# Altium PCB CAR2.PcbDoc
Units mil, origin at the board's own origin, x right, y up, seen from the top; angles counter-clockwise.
Board outline 1397.98 x 964.91 mil, 2 copper layers (Top Layer, Bottom Layer); 47 components, 32 nets, 165 pads, 34 vias.
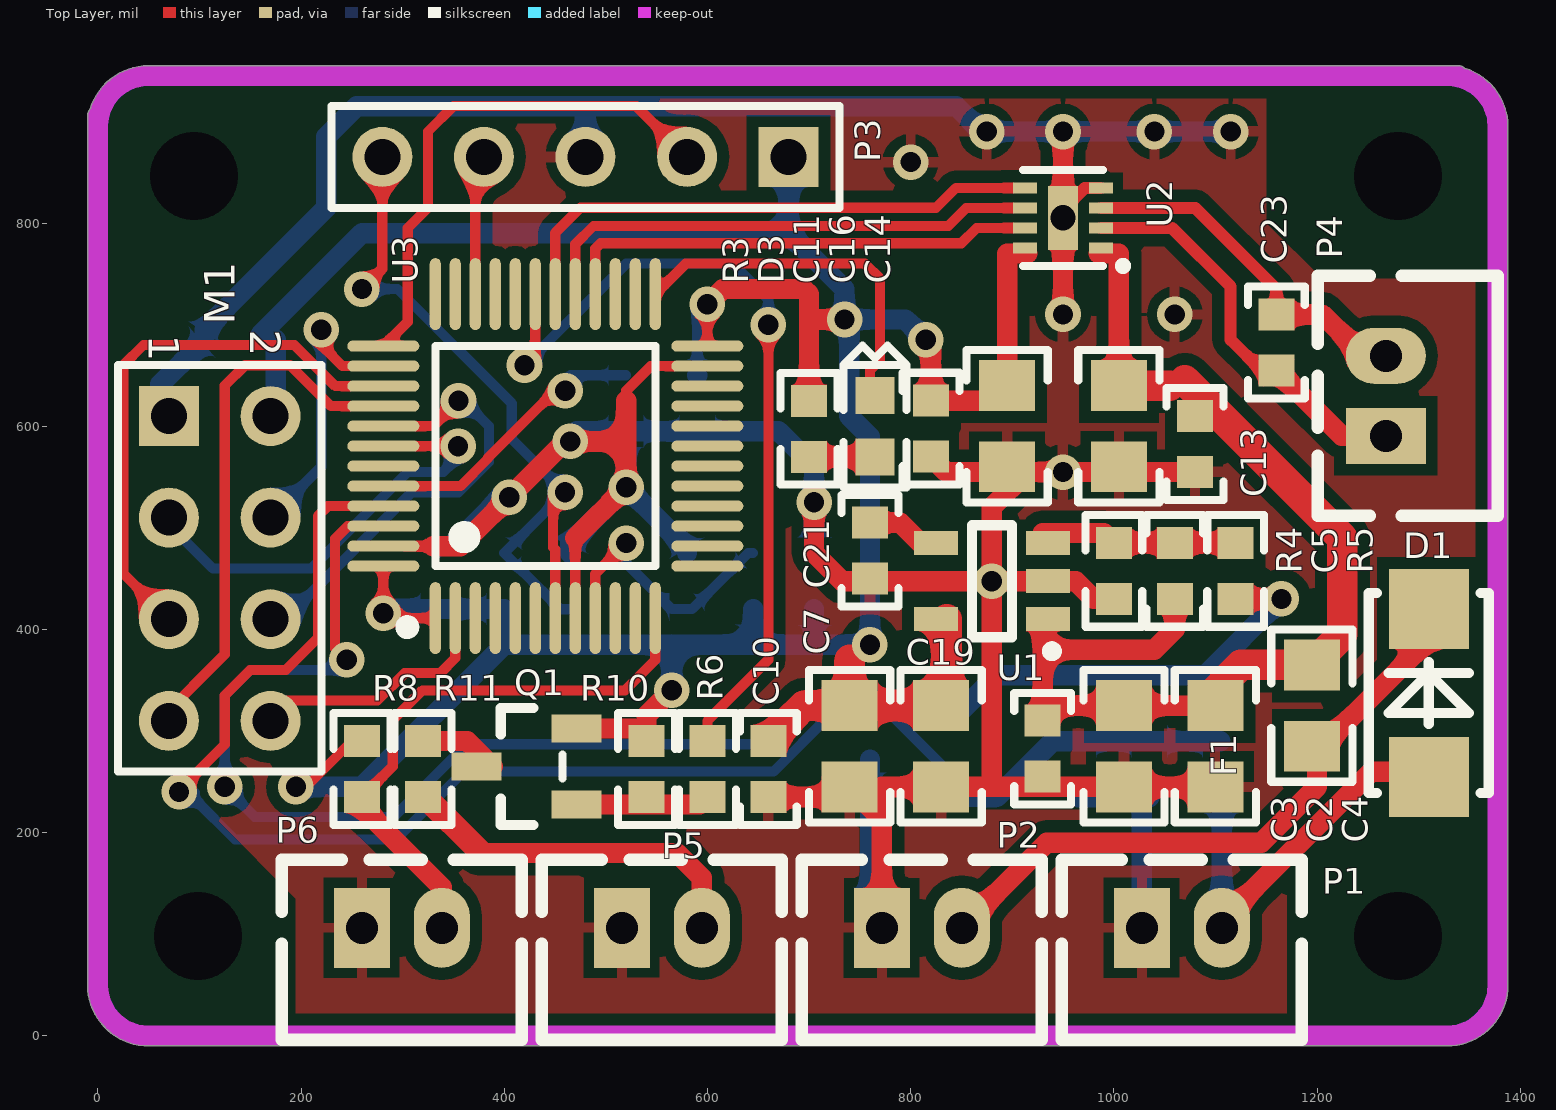
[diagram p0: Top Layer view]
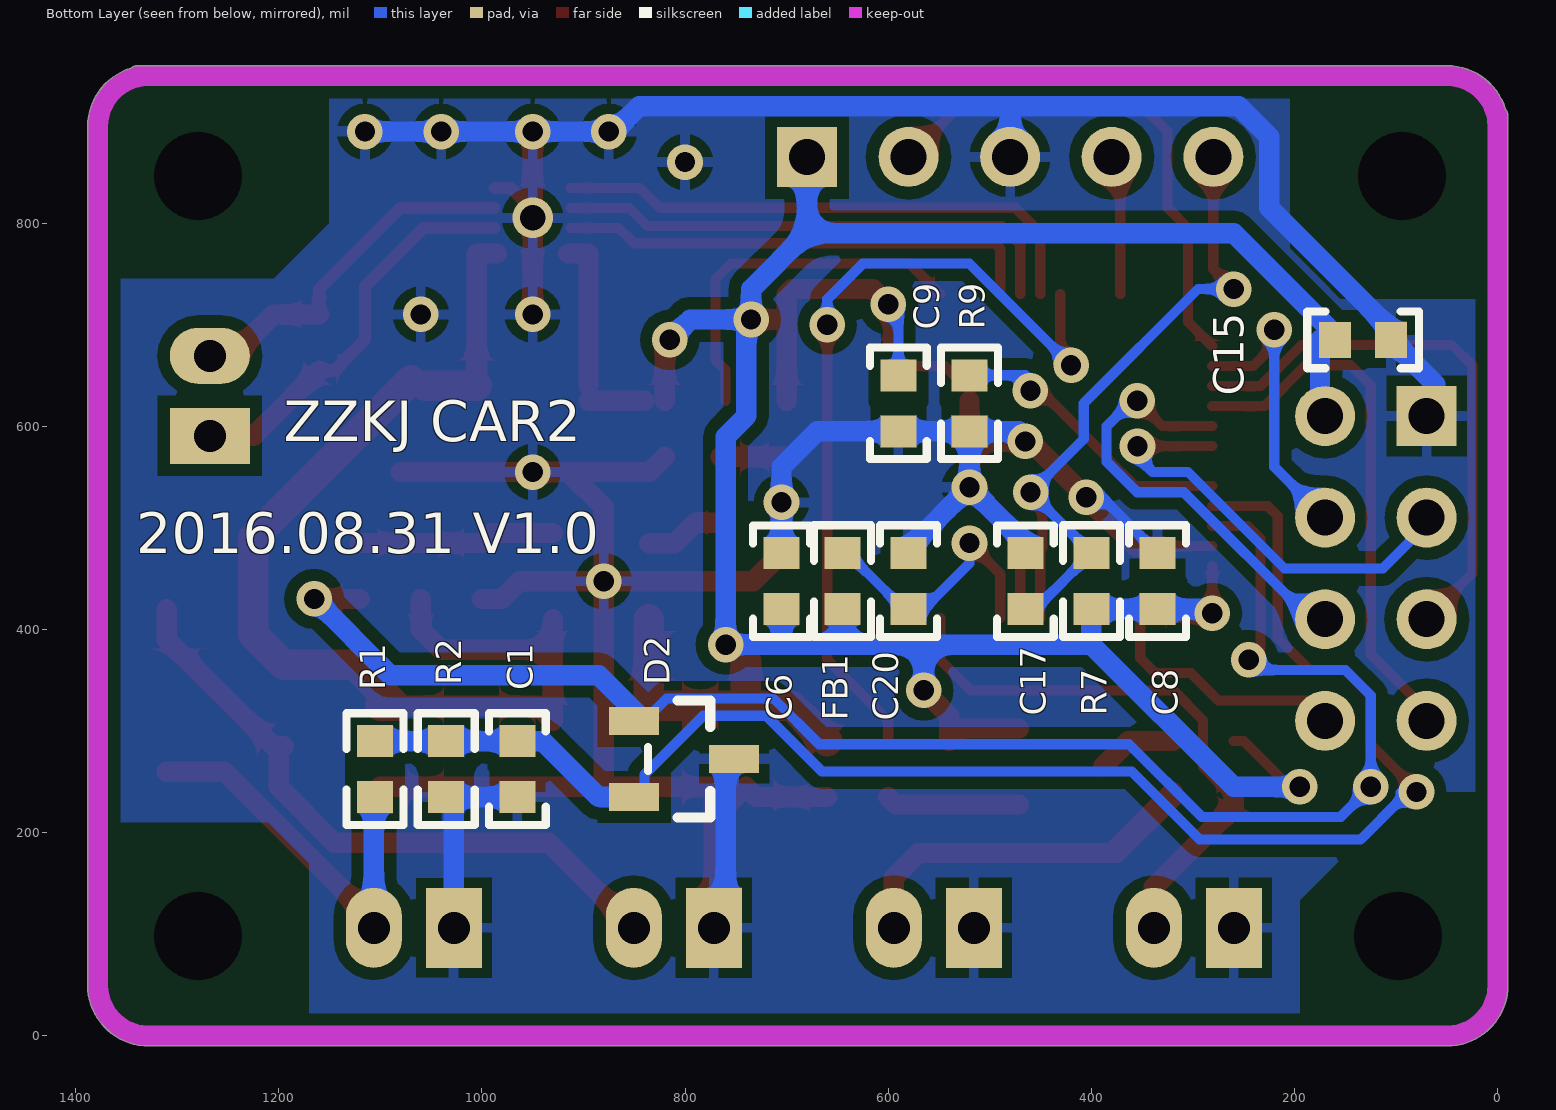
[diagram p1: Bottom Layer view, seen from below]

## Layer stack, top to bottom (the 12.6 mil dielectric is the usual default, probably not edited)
Top Solder: solder mask 0.4, Solder Resist, Dk 3.5
Top Layer: signal copper 1.4
Dielectric 1: dielectric 12.6, FR-4, Dk 4.8
Bottom Layer: signal copper 1.4
Bottom Solder: solder mask 0.4, Solder Resist, Dk 3.5

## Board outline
-10.01,50 -10.01,905.51 cw(c0,905.51) -7.47,912.19 cw(c50,894.88) 50,954.9 1338.58,954.9 cw(c1338.58,944.88) 1345.26,952.35 cw(c1327.95,894.88) 1387.97,894.88 1387.97,50 cw(c1327.95,50) 1327.95,-10.01 50,-10.01 cw(c50,50)

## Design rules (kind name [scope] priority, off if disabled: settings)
Clearance Clearance_1 [InPolygon] p1: gap=12
Clearance [All] p2: gap=7
PolygonConnect [All] p1: connectstyle=Relief reliefconductorwidth=10 reliefentries=4 polygonreliefangle="90 Angle" airgapwidth=10
RoutingVias [All] p1: holewidth=22 width=40 viastyle="Through Hole" minholewidth=20 minwidth=30 maxholewidth=30 maxwidth=50
SilkToSolderMaskClearance [IsPad] p1: minsilkscreentomaskgap=4 clearancetoexposedcopper=TRUE
SolderMaskExpansion [All] p1: expansion=4
Width [All] p1: maxlimit=50 minlimit=10 preferedwidth=20 minimp=50.000000 maximp=50.000000 favimp=50.000000
29 further rules are at their usual default settings.

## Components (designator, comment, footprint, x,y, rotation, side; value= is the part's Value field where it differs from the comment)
C1 "100nF" C0603 965,234.88 r90 bottom
C2 "10uF" C0805 1010,285 r270 top
C3 "100nF" C0603 930,255 r90 top
C4 "10uF" C0805 1100,285 r270 top
C5 "100nF" C0603 1060,485.12 r270 top
C6 "100nF" C0603 705,419.88 r90 bottom
C7 "10uF" C0805 740,285 r270 top
C8 "100nF" C0603 335,475.12 r270 bottom
C9 "100nF" C0603 590,595 r90 bottom
C10 "100nF" C0603 660,290.12 r270 top
C11 "100nF" C0603 820,570 r90 top
C13 "100nF" C0603 1080,554.88 r90 top
C14 "10uF" C0805 1005,600 r90 top
C15 "100nF" C0603 105,685 r0 bottom
C16 "10uF" C0805 895,600 r90 top
C17 "100nF" C0603 465,475 r270 bottom
C19 "10uF" C0805 830,285 r90 top
C20 "100nF" C0603 580,475.12 r270 bottom
C21 "100nF" C0603 760,505 r270 top
C23 "100nF" C0603 1160,710 r270 top
D1 "SS14" LC-SMA(DO-214AC)_S2 1310,337.32 r270 top
D2 "PESD3V3L2BT" LC-SOT-23(SOT-23-3) 800.79,272.4 r0 bottom
D3 "LEDV1" LC-0603_LED_S4 765,600 r270 top
F1 "SMD0805-110" R0805 1195,325 r90 top
FB1 "GZ1608D601TF" R0603 645,420 r90 bottom
M1 "NRF2401" HDR2X4 70,610 r270 top
P1 "5V IN" PH-2Y 1027.56,106.3 r0 top
P2 "BAT" PH-2Y 771.65,106.3 r0 top
P3 "SWD" HDR1X5 680,865 r180 top
P4 "Motor" PH-2Y 1267.72,590.55 r90 top
P5 "TX" PH-2Y 515.75,106.3 r0 top
P6 "RX" PH-2Y 259.84,106.3 r0 top
Q1 "Si2301CDS" LC-SOT-23(SOT-23-3) 422.13,265 r0 top
R1 "10K" R0603 1105,290 r270 bottom
R2 "10K" R0603 1035,234.88 r90 bottom
R3 "1.5K" R0603 700,569.88 r90 top
R4 "100K" R0603 1000,430 r90 top
R5 "10K" R0603 1120,430 r90 top
R6 "1K" R0603 600,235 r90 top
R7 "100K" R0603 400,475.12 r270 bottom
R8 "100K" R0603 260,290.12 r270 top
R9 "10K" R0603 520,595 r90 bottom
R10 "100K" R0603 540,290.12 r270 top
R11 "100" R0603 320,290.12 r270 top
U1 "MIC5205-3.3YM5" LC-SOT-23-5 880,447.4 r0 top
U2 "DRV8837DSGR" "LC-WSON-8_2x2mm - DRV8837" 950,805 r90 top
U3 "STM32F051C8T6" LC-LQFP-48_7x7x05P 440.47,570.55 r0 top

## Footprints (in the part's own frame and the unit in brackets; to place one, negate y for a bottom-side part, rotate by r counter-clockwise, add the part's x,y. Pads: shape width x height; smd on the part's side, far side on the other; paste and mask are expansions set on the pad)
C0603 [mm] "Chip Capacitor, Body 1.6x0.8mm, IPC High Density"
  rect 0.8x0.9 smd: 1(0,0) 2(1.4,0)
  silkscreen extent -0.7,-0.71 2.1,0.71, body extent -0.18,-0.48 1.57,0.47, height 1.3
C0805 [mil] "Chip Capacitor, Body 2.0x1.3mm, IPC High Density"
  rect 50x55.12 smd: 1(-40,0) 2(40,0)
  silkscreen extent -75,-40 75,40, body extent -43,-30 43,30, height 55
HDR1X5 [mm] "Connector; Header; 5 Position"
  rect 1.5x1.5 hole 0.9: 1(0,0)
  round 1.5 hole 0.9: 2(2.54,0) 3(5.08,0) 4(7.62,0) 5(10.16,0)
  silkscreen extent -1.27,-1.27 11.43,1.27
HDR2X4 [mm] "Connector; Header; 4x2 Position"
  rect 1.5x1.5 hole 0.9: 1(0,0)
  round 1.5 hole 0.9: 2(0,2.54) 3(2.54,0) 4(2.54,2.54) 5(5.08,0) 6(5.08,2.54) 7(7.62,0) 8(7.62,2.54)
  silkscreen extent -1.27,-1.27 8.89,3.81
LC-0603_LED_S4 [mm]
  rect 0.93x0.98 smd: A(0.77,0) K(-0.77,0)
  silkscreen extent -2.01,-0.79 1.54,0.79, body extent -0.8,-0.4 0.8,0.4, height 0.6
LC-LQFP-48_7x7x05P [mm]
  oval 0.28x1.8 smd mask+0.051: 1(-2.75,-4.05) 2(-2.25,-4.05) 3(-1.75,-4.05) 4(-1.25,-4.05) 5(-0.75,-4.05) 6(-0.25,-4.05) 7(0.25,-4.05) 8(0.75,-4.05) 9(1.25,-4.05) 10(1.75,-4.05) 11(2.25,-4.05) 12(2.75,-4.05) 25(2.75,4.05) 26(2.25,4.05) 27(1.75,4.05) 28(1.25,4.05) 29(0.75,4.05) 30(0.25,4.05) 31(-0.25,4.05) 32(-0.75,4.05) 33(-1.25,4.05) 34(-1.75,4.05) 35(-2.25,4.05) 36(-2.75,4.05)
  oval 1.8x0.28 smd mask+0.051: 13(4.05,-2.75) 14(4.05,-2.25) 15(4.05,-1.75) 16(4.05,-1.25) 17(4.05,-0.75) 18(4.05,-0.25) 19(4.05,0.25) 20(4.05,0.75) 21(4.05,1.25) 22(4.05,1.75) 23(4.05,2.25) 24(4.05,2.75) 37(-4.05,2.75) 38(-4.05,2.25) 39(-4.05,1.75) 40(-4.05,1.25) 41(-4.05,0.75) 42(-4.05,0.25) 43(-4.05,-0.25) 44(-4.05,-0.75) 45(-4.05,-1.25) 46(-4.05,-1.75) 47(-4.05,-2.25) 48(-4.05,-2.75)
  silkscreen extent -3.6,-4.42 2.75,2.75
LC-SMA(DO-214AC)_S2 [mm]
  rect 2x2 smd: 1(2.1,0) 2(-2.1,0)
  silkscreen extent -2.5,-1.5 2.5,1.5
LC-SOT-23(SOT-23-3) [mm]
  rect 1.25x0.7 smd: 1(1.25,-0.95) 2(1.25,0.95) 3(-1.25,0)
  silkscreen extent -0.65,-1.46 0.9,1.46, body extent -1.5,-1.5 1.5,1.5, height 1.3
LC-SOT-23-5 [mm]
  rect 1.1x0.6 smd: 1(1.4,-0.95) 2(1.4,0) 3(1.4,0.95) 4(-1.4,0.95) 5(-1.4,-0.95)
  silkscreen extent -0.5,-1.87 1.63,1.4
"LC-WSON-8_2x2mm - DRV8837" [mm]
  rect 1.6x0.762 smd mask+0.051: 0(0,0)
  rect 0.28x0.6 smd mask+0.051: 1(-0.75,-0.95) 2(-0.25,-0.95) 3(0.25,-0.95) 4(0.75,-0.95) 5(0.75,0.95) 6(0.25,0.95) 7(-0.25,0.95) 8(-0.75,0.95)
  silkscreen extent -1.3,-1.6 1.2,1
PH-2Y [mm]
  rect 1.4x2 hole 0.8: 1(0,0)
  oval 1.4x2 hole 0.8: 2(2,0)
  silkscreen extent -2,-2.8 4,1.7
R0603 [mm] "Chip Capacitor, Body 1.6x0.8mm, IPC High Density"
  rect 0.8x0.9 smd: 1(0,0) 2(1.4,0)
  silkscreen extent -0.7,-0.71 2.1,0.71, body extent -0.18,-0.48 1.57,0.47, height 1.3
R0805 [mil] "Chip Capacitor, Body 2.0x1.3mm, IPC High Density"
  rect 50x55.12 smd: 1(-40,0) 2(40,0)
  silkscreen extent -75,-40 75,40, body extent -43,-30 43,30, height 55

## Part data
C1 C3 C5 C8 C9 C10 C11 C13 C14 C15 C16 C17 C19 C20 C21 C23: library part Cap, "Capacitor"
C2 C4 C6 C7: library part CAP, "Capacitor"
D1: library part DIODE, "Diode"
D2: library part ZENER2, "TVS"
D3: library part LED2, "Typical RED, GREEN, YELLOW, AMBER GaAs LED"
F1: library part "Fuse 2", "Fuse"
FB1: library part INDUCTOR1
P1 P2 P4 P5 P6: library part "Header 2", "Header, 2-Pin"
P3: library part "Header 5", "Header, 5-Pin"
Q1: library part BSH201, "P-channel Enhancement Mode MOSFET"
R1 R2 R3 R4 R5 R6 R7 R8 R9 R10 R11: library part Res2, "Resistor"
U1: library part MIC5205, "150mA Low-Noise LDO Regulator"
U2: library part DRV883x, "Low-Voltage H-Bridge Driver"
U3: library part STM32F51C8T6, "STM32 ARM-based 32-bit MCU with 64 Kbytes Flash, 48-pin LQFP, Industrial Temperature"

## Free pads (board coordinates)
  round 0 hole 86.61 unplated: 1(98.43,98.43) 2(94.49,846.46) 3(1279.53,846.46) 4(1279.53,98.43)

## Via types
v1: diameter 35, hole 20, Top Layer to Bottom Layer, tented both sides, 32 vias
v2: diameter 35, hole 20, Top Layer to Bottom Layer, 1 vias
v3: diameter 30/40 (per signal layer), hole 25, Top Layer to Bottom Layer, 1 vias

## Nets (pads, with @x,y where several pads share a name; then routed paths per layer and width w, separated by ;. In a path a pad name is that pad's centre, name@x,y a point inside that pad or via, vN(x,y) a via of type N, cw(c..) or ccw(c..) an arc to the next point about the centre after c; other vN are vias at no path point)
BOOT0: R9.2 U3.44 | length 290.6
  Top Layer w10: U3.44 356.96,541.02 384.11,568.17 384.11,569.11 450,635 v1(460,635)
  Bottom Layer w10: v1(460,635) 460,645 465.12,650.12 R9.2
GND: C1.1 C2.2 C3.1 C4.2 C6.2 C7.2 C8.1 C9.1 C10.2 C11.1 C13.1 C14.1 C15.1 C16.1 C17.1 C19.1 C20.1 C21.2 D2.3 M1.1 P1.1 P2.1 P3.3 P5.1 P6.1 R2.1 R4.1 R9.1 U1.2 U2.0 U2.4 U3.8 U3.23 U3.47 | length 4709.6
  Top Layer w10: U3.47 330,481.97 ; U3.8 470,490 ; 520,625 520,635 544.13,659.13 U3.23
  Top Layer w12: U2.0@950,813.15 971.38,834.53 U2.4
  Top Layer w20: 330,481.97 356.97,481.97 v1(405,530) v1@462.5,587.5 ; v1(465,585) 520,585 ; 470,490 v1(520,540) 520,585 ; 520,625 520,585 ; C10.2 730,235 C7.2 771.65,213.35 ; v1(705,525) 705,475 732.6,447.4 v2(880,447.4) ; P2.1 771.65,213.35 ; C11.1 835.12,554.88 C16.1@914.88,554.88 ; v1(950,710) v3(950,805) 950,813.15 v1(950,890) ; R4.1 980,430 962.6,447.4 v2(880,447.4) ; C13.1 v1(950,554.88) C16.1@914.88,554.88 ; C4.2 C2.2 880,245 ; 771.65,213.35 771.65,245 C19.1 880,245 ; 880,245 v2(880,447.4) ; v2(880,447.4) 880,520 C16.1@914.88,554.88
  Bottom Layer w10: C8.1 389.88,530 v1(405,530)
  Bottom Layer w20: M1.1@61.42,611.81 61.42,641.42 C15.1 105,695 225,815 225,885 255,915 485,915 ; C17.1 465,485 v1(520,540) ; v1@471.21,595 R9.1 C9.1 670,595 705,560 v1(705,525) C6.2 ; P3.3 480,910 485,915 ; R9.1@520,580 v1(520,540) ; C20.1 580,480 v1(520,540) ; D2.3@760,272 760,117.95 P2.1 ; C1.1 R2.1@1027.56,234.88 ; P1.1 R2.1@1027.56,234.88 ; R2.1 R2.1@1027.56,234.88 ; v1(1115,890) v1(1040,890) v1(950,890) v1(875,890) 870,890 845,915 485,915
  other v1: 1060,710 800,860
IR_RX: P6.2 R8.2 U3.12 | length 573.8
  Top Layer w10: R8.2 290.28,265.28 290.28,310.84 319.45,340 518.89,340 548.74,369.85 U3.12
  Top Layer w20: R8.2 260,225 338.58,146.42 P6.2
IR_TX: R6.2 U3.31 | length 830.1
  Top Layer w10: v1(420,660) 430.63,670.63 U3.31 ; R6.2 600,310 660,370 v1(660,700)
  Bottom Layer w10: v1(420,660) 520,760 625,760 660,725 v1(660,700)
LED: D3.K U3.25 | length 363.9
  Top Layer w10: U3.25 578.74,760 755,760 770,745 770,665 760,655 D3.K@760,625.12
MIN1: U2.6 U3.29 | length 506.5
  Top Layer w10: U3.29 470,779.04 487.96,797 837,797 854.84,814.84 U2.6
MIN2: U2.5 U3.30 | length 540.9
  Top Layer w10: U3.30 450.31,790.31 475,815 825,815 844.53,834.53 U2.5
MNSLEEP: U2.7 U3.28 | length 476.1
  Top Layer w10: U3.28 489.68,774.68 495,780 850,780 865.16,795.16 U2.7
NetC5_1: C5.1 R4.2 R5.2 U1.3 | length 194
  Top Layer w20: U1.3@930,494.8 990.32,494.8 R4.2 C5.1 R5.2
NetC20_2: C20.2 FB1.2 U3.9 | length 272.9
  Top Layer w10: U3.9 489.68,454.68 v1(520,485)
  Bottom Layer w10: v1(520,485) 520,465 565,420 C20.2 585,420 640.12,475.12 FB1.2
NetC21_1: C21.1 U1.4 | length 84.3
  Top Layer w20: C21.1 789.8,505 810,484.8 835.51,484.8 U1.4@835.2,485.12
NetC23_1: C23.1 P4.2 U2.3 | length 355.2
  Top Layer w12: U2.3 1080.16,814.84 1160,735 C23.1
  Top Layer w20: C23.1 1205,710 1245.71,669.29 P4.2
NetC23_2: C23.2 P4.1 U2.2 | length 395.8
  Top Layer w12: U2.2 1057.34,795.16 1115,737.5 1115,685 1145.12,654.88 C23.2
  Top Layer w20: C23.2 1224.33,590.55 P4.1
NetD1_1: D1.1 P1.2 R1.2 | length 400.5
  Top Layer w20: P1.2 1106.3,113.12 1253.18,260 D1.1@1310,260
  Bottom Layer w20: R1.2 1106.3,233.58 P1.2
NetD3_A: D3.A R3.1 | length 65.1
  Top Layer w20: R3.1 764.8,569.88 D3.A
NetP5_2: P5.2 R11.2 | length 441.5
  Top Layer w20: R11.2 375,180 380,180 ; R11.2@320,240 380,180 ; P5.2 594.49,155.51 570,180 380,180
NetQ1_1: Q1.1 R6.1 R10.2 | length 131.7
  Top Layer w20: Q1.1 592.6,227.6 R6.1
NetQ1_3: Q1.3 R11.1 | length 79.1
  Top Layer w20: R11.1 363.54,290.12 Q1.3@388.66,265
NRST: C17.2 P3.5 R7.1 U3.7 | length 743.9
  Top Layer w10: v1(260,735) 280,755 P3.5 ; U3.7 450.31,478.57 448,480.89 448,523.12 v1(459.88,535)
  Bottom Layer w10: v1(260,735) 295,735 407.5,622.5 407.5,587.38 v1(459.88,535) R7.1 455.24,419.88 C17.2
PWR: D2.1 R5.1 U3.46 | length 1605.4
  Top Layer w10: v1(245,370) 233.59,381.41 233.59,489.39 245.86,501.65 U3.46
  Top Layer w20: R5.1 v1(1165,430)
  Bottom Layer w10: v1(245,370) 235,360 150,360 125,335 v1(125,245) 154.5,215.5 291.46,215.5 362.96,287 667.96,287 712.96,332 818,332 D2.1@840,310
  Bottom Layer w20: D2.1@840,310 885,355 1090,355 v1(1165,430)
RF_CE: M1.3 U3.42 | length 444.4
  Top Layer w10: U3.42 v1(354.61,580.39)
  Bottom Layer w10: M1.3@61.42,511.81 113.23,460 210,460 305,555 340,555 354.61,569.61 v1(354.61,580.39)
RF_IRQ: M1.8 U3.2 | length 255
  Top Layer w10: M1.8 167.66,310 165.85,311.81 184.04,330 275,330 302,357 337,357 351.89,371.89 U3.2
SPI1_MISO: M1.7 U3.40 | length 535.5
  Top Layer w10: M1.7@61.42,311.81 125,375.39 125,640 145,660 189.24,660 229.48,619.76 U3.40
SPI1_MOSI: M1.6 U3.41 | length 439.6
  Top Layer w10: U3.41 330.08,600.08 v1@350,620
  Bottom Layer w10: M1.6@161.42,411.81 185.85,411.81 309.04,535 355,535 385,565 385,600 360,625 v1(355,625)
SPI1_NSS: M1.4 U3.38 | length 290.4
  Top Layer w10: v1(220,695) 220,680 240.87,659.13 U3.38
  Bottom Layer w10: M1.4 220,560 v1(220,695)
SPI1_SCK: M1.5 U3.39 | length 554.5
  Top Layer w10: M1.5@61.42,411.81 M1.5@64.8,415.2 ; M1.5 M1.5@64.8,415.2 ; U3.39 233.83,639.45 193.28,680 45,680 25,660 25,455 M1.5@64.8,415.2
SWCLK: P3.2 U3.37 | length 515.5
  Top Layer w10: U3.37 305,702.8 305,795 325,815 325,890 350,915 530,915 P3.2
SWDIO: P3.4 U3.34 | length 138.5
  Top Layer w10: U3.34 371.57,856.57 P3.4
VBAT: D1.2 F1.1 P2.2 | length 635.6
  Top Layer w20: P2.2 934.09,190 1145,190 1200,245 F1.1@1200,285 ; F1.1 F1.1@1200,285 ; D1.2 1310,390 1205,285 F1.1@1200,285
VBUS: C1.2 D2.2 R1.1 R2.2 U3.45 | length 1567.2
  Top Layer w10: v1@80,241.72 125,286.72 125,335 150,360 185,360 216.59,391.59 216.59,511.59 226.34,521.34 U3.45
  Bottom Layer w10: v1@95.5,239.5 95.5,232.78 135,193.28 293.28,193.28 360,260 665,260 720,315 782.03,315 840,257.03 D2.2@840,235
  Bottom Layer w20: D2.2@840,235 D2.2 885,235 940,290 C1.2 R2.2 R1.1
  other v1: 80,240
VCC3.3: C6.1 C7.1 C8.2 C9.2 C10.1 C11.2 C15.2 C16.2 C19.2 FB1.1 M1.2 P3.1 Q1.2 R3.2 R7.2 R8.1 R10.1 U1.5 U2.8 U3.1 U3.24 U3.48 | length 3431.8
  Top Layer w10: v1@195,235 250.12,290.12 R8.1 ; U3.48 v1(281.02,416.02) 285.94,411.1 U3.1 ; U3.24 v1(599.92,719.92)
  Top Layer w20: Q1.2 527.72,302.4 R10.1 540,315 v1(565,340) ; v1(599.92,719.92) 615,735 695,735 700,730 700,700 ; R3.2 700,700 ; v1(735,705) 705,705 700,700 ; v1(815,685) 820,680 C11.2 ; 840,625.12 C16.2@895,625.12 ; C16.2 895,770 U2.8@915,770
  Top Layer w30: C10.1 694.88,325 C7.1 ; 740,370 C7.1 ; U1.5@835.51,410 835.51,330.51 C19.2 C7.1
  Bottom Layer w10: C9.2 590,710 v1(599.92,719.92)
  Bottom Layer w20: C15.2 160.12,690.12 260,790 680,790 ; M1.2@173.23,600 161.42,611.81 175,625.39 C15.2@175,685 ; v1(195,245) 260,245 400,385 ; v1(281.02,416.02) 285,420 C8.2 R7.2 396.02,416.02 400,412.05 400,385 ; v1(565,340) 565,385 ; C9.2 C9.2@590.12,650 ; FB1.1 645,385 ; P3.1 680,790 ; C6.1 705,387.5 702.5,385 ; v1(815,685) 795,705 v1(735,705) ; 400,385 565,385 ; 565,385 645,385 ; 645,385 702.5,385 ; 680,790 735,735 v1(735,705) ; 702.5,385 v1(760,385) 760,589.72 739.72,610 739.72,700.28 v1(735,705)
VIN: C2.1 C3.2 C4.1 C5.2 C13.2 C14.2 F1.2 U1.1 U2.1 | length 1127.5
  Top Layer w20: U1.1@930,410 930,380 ; U2.1@985,770 1005,770 C14.2 ; C5.2 1060,400 1040,380 930,380 ; C4.1@1085,325 C2.1 944.88,325 C3.2 930,380
  Top Layer w30: C14.2 1055,640 ; 1070,645 1225,490 1225,395 F1.2 1125,365 1085,325 C4.1
pads on no net: U3.3 U3.4 U3.5 U3.6 U3.10 U3.11 U3.13 U3.14 U3.15 U3.16 U3.17 U3.18 U3.19 U3.20 U3.21 U3.22 U3.26 U3.27 U3.32 U3.33 U3.35 U3.36 U3.43

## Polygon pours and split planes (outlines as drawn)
GND on Bottom Layer "GND_L02_P006" (solid, remove dead copper, pour order 6): 1150,944.88 1150,800 1205,745 1380,745 1380,212.05 1377.95,210 1210,210 1175,175 1170,170 1170,0 195,0 195,133.28 160.28,168 88.28,240 0,240 0,690 0,715 0,725 155,725 175,745 205,775 205,944.88
GND on Top Layer "GND_L01_P008" (solid, remove dead copper, pour order 8): 1150,944.88 1150,800 1205,745 1377.95,745 1377.95,210 1195,210 1170,185 1170,0 195,0 195,135 90,240 0,240 0,725 120,725 205,810 205,944.88

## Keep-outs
Keep-Out Layer:
  lines w20: 0,894.88 cw(c50,894.88) 50,944.88 1338.58,944.88 ; 0,905.51 0,50 ccw(c50,50) 50,0 1327.95,0 ccw(c1327.95,50) 1377.95,50 1377.95,894.88 ccw(c1327.95,894.88) 1327.95,944.88

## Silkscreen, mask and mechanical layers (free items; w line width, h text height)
Bottom Overlay:
  text "ZZKJ CAR2" at 1195,585 h40
  text "2016.08.31 V1.0" at 1340,475 h40
Drill Drawing:
  text ".Legend" at -40,1240 h50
